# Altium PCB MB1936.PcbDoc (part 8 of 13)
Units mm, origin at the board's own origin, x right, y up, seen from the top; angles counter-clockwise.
Board outline 172 x 137 mm, 6 copper layers (Top Layer, Signal Layer 1, Signal Layer 2, Signal Layer 3, Signal Layer 4, Bottom Layer), stack 1.549 mm thick; 859 components, 672 nets, 3477 pads, 2222 vias.
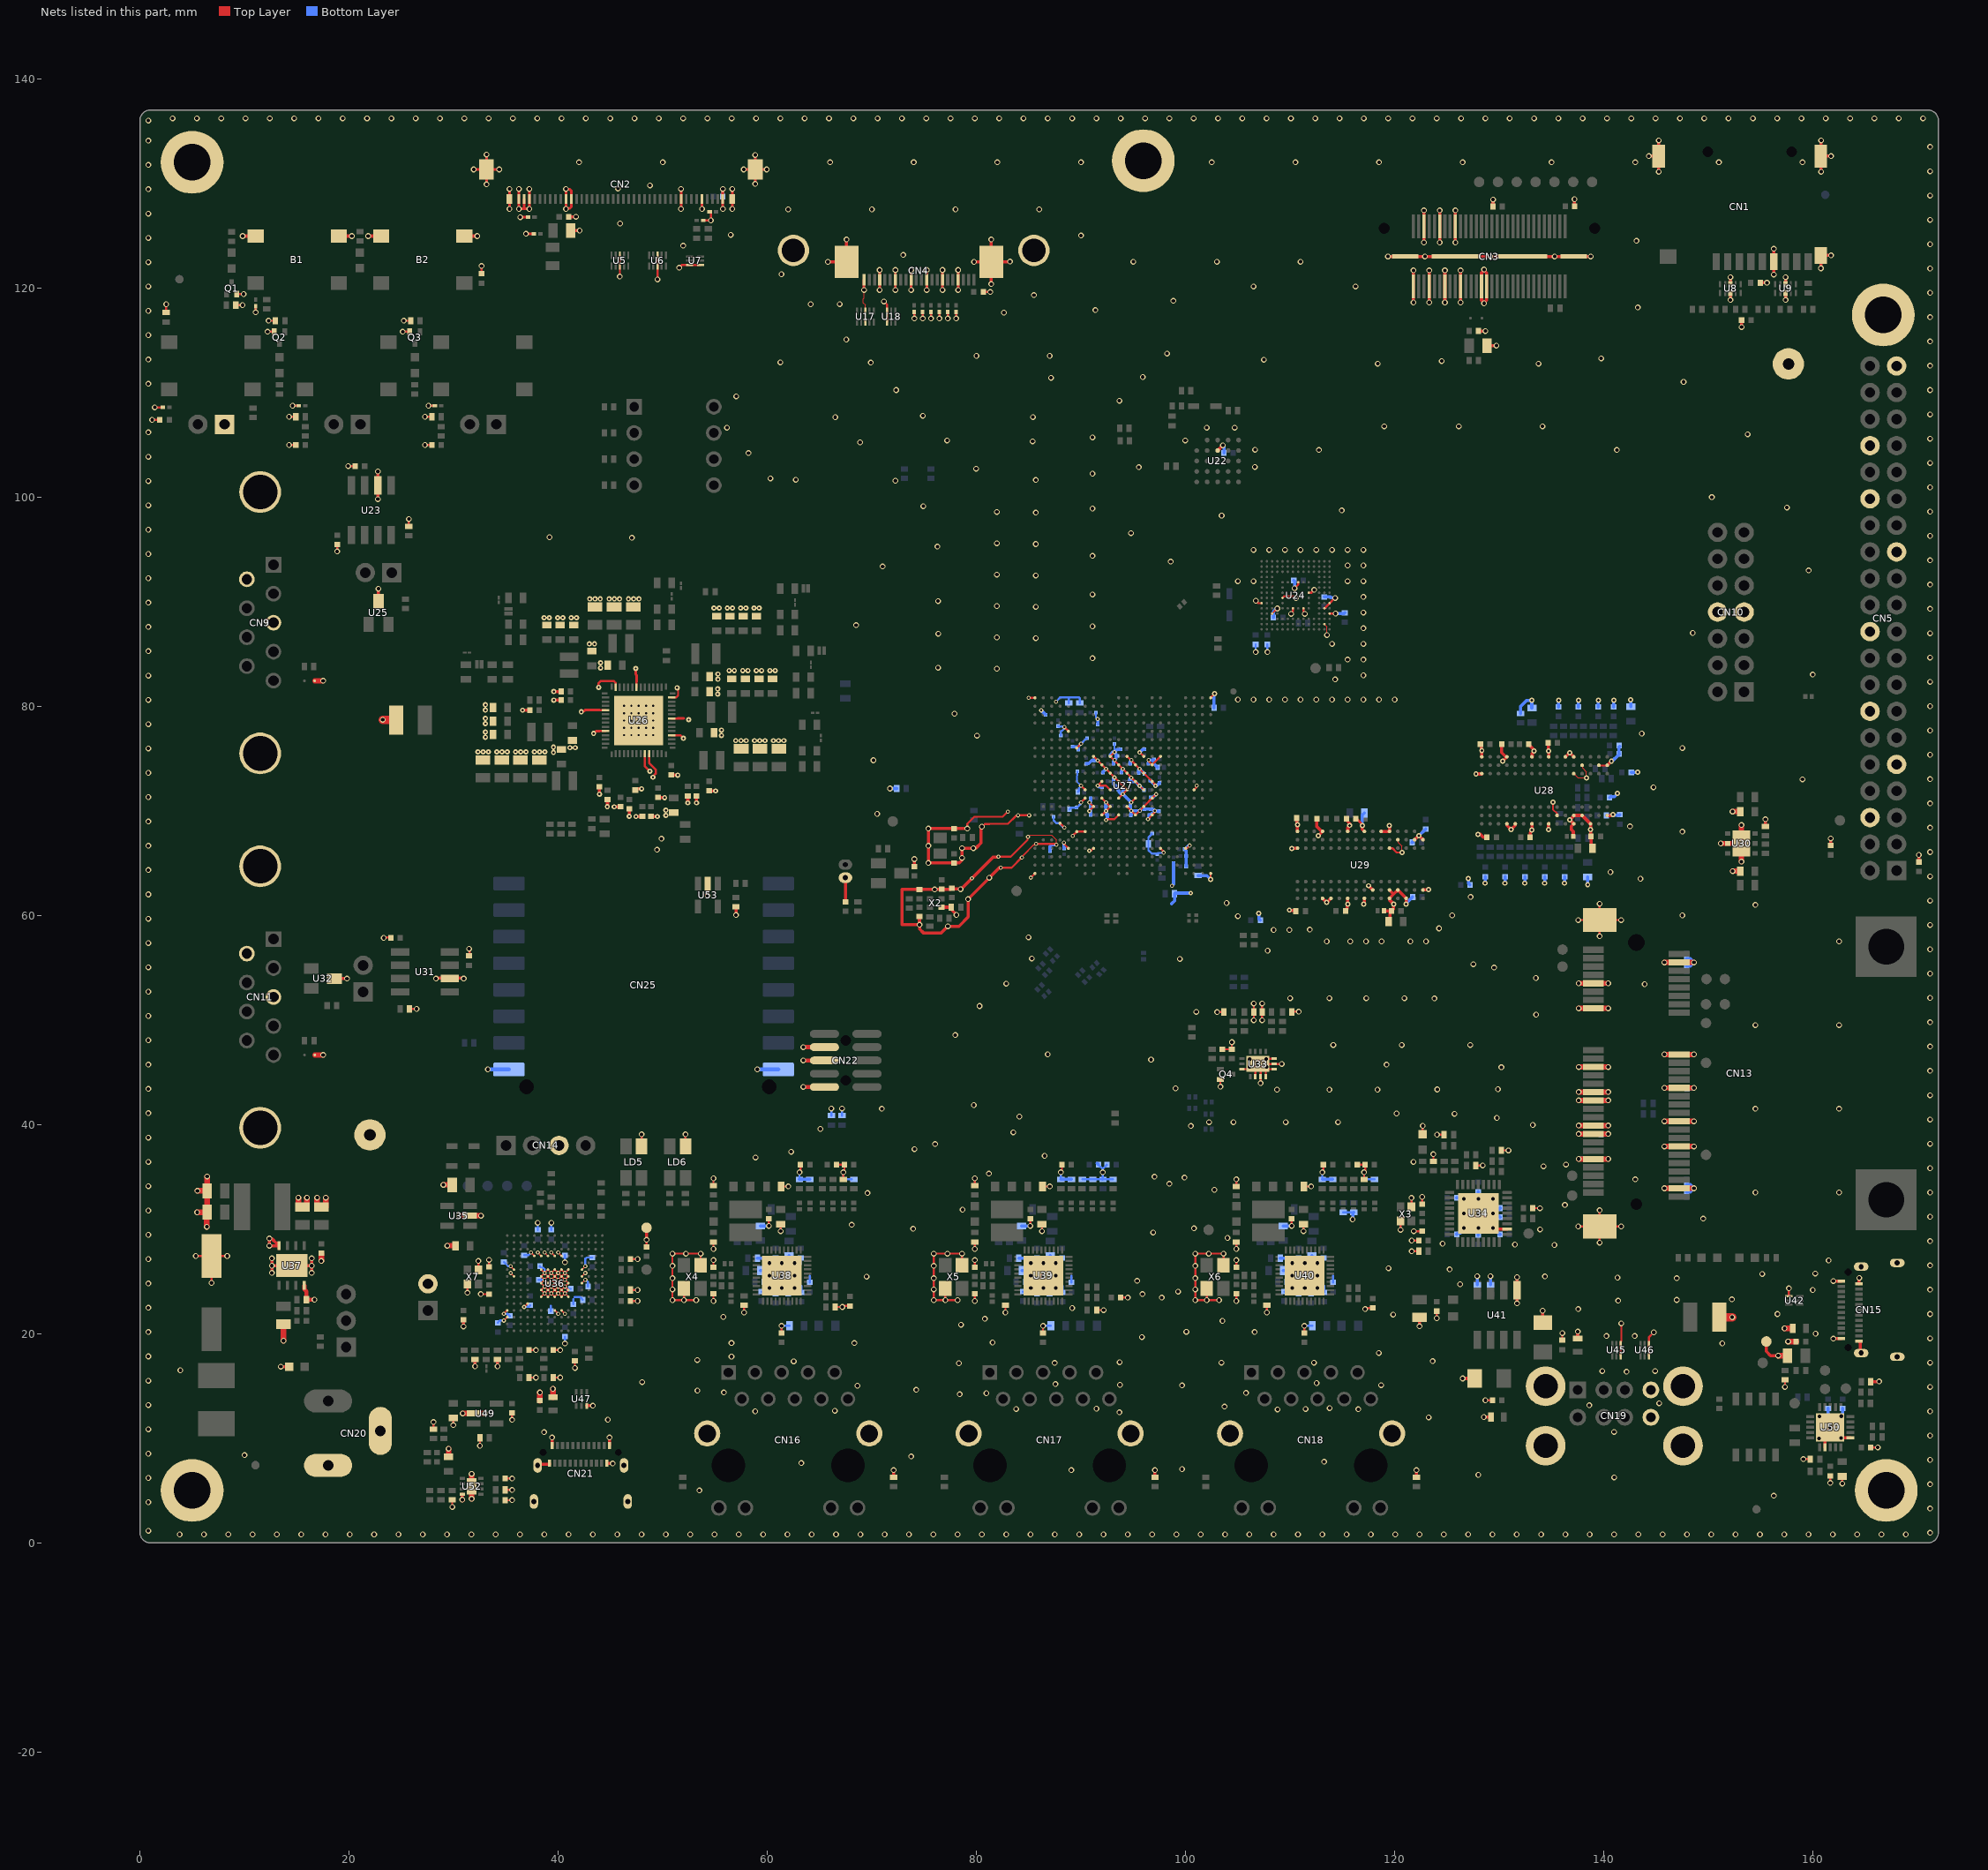
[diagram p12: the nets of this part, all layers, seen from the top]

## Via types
v1: diameter 0.55, hole 0.35, Top Layer to Bottom Layer, 1661 vias
v2: diameter 0.4, hole 0.2, Top Layer to Bottom Layer, tented both sides, 253 vias
v3: diameter 0.5, hole 0.2, Top Layer to Bottom Layer, 157 vias
v4: diameter 0.5, hole 0.25, Top Layer to Bottom Layer, 145 vias
v5: diameter 0.4, hole 0.2, Top Layer to Bottom Layer, 6 vias

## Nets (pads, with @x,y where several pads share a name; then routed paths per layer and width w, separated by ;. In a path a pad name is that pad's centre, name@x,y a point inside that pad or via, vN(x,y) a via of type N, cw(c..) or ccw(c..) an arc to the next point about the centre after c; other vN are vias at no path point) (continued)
GND: B1.3 B1.4 B2.1 B2.2 C1.1 C2.1 C3.1 C4.1 C5.1 C6.1 C7.1 C8.1 C9.1 C10.1 C11.1 C12.1 C13.1 C14.2 C15.1 C16.1 C17.1 C18.1 C21.1 C22.1 C23.1 C24.1 C26.1 C27.1 C28.1 C29.1 C30.1 C32.1 C34.1 C35.1 C36.1 C37.1 C38.1 C39.1 C40.1 C41.1 C42.2 C43.2 C44.1 C45.1 C46.1 C47.1 C48.1 C49.1 C50.1 C51.1 C52.1 C53.1 C54.1 C56.1 C57.1 C58.1 C59.1 C60.1 C61.1 C62.1 C63.2 C64.1 C65.2 C66.1 C67.1 C68.1 C69.2 C70.1 C71.1 C72.2 C73.2 C74.2 C75.2 C76.1 C77.1 C78.1 C79.1 C80.1 C81.2 C82.1 C83.1 C84.1 C85.1 C86.2 C87.1 C88.1 C89.1 C90.1 C91.1 C92.2 C93.1 C94.1 C95.1 C96.1 C99.1 C100.2 C101.1 C102.1 C103.1 C104.1 C105.1 C106.1 C107.1 C108.1 C109.1 C110.1 C111.1 C112.1 C113.2 C114.1 C115.1 C116.1 C117.1 C118.1 C119.1 C120.1 C121.1 C122.1 C123.1 C124.1 C125.1 C126.1 C127.2 C128.1 C129.1 C130.1 C131.1 C132.1 C133.2 C134.1 C135.1 C136.1 C137.1 C138.1 C139.1 C140.1 C141.1 C142.1 C143.1 C144.1 C145.1 C146.1 C147.2 C148.1 C149.1 C150.1 C152.1 C153.1 C154.1 C155.1 C156.1 C157.2 C158.2 C159.1 C160.1 C161.1 C163.1 C164.2 C165.1 C166.1 C168.1 C169.1 C170.1 C171.1 C172.1 C173.1 C174.1 C175.1 C177.1 C178.1 C179.1 C180.1 C181.1 C182.1 C183.1 C184.1 C185.1 C186.1 C187.1 C188.1 C189.1 C190.1 C191.1 C192.1 C193.1 C194.1 C195.1 C196.1 C197.1 C198.1 C199.1 C200.2 C201.1 C202.1 C203.1 C204.2 C205.1 C206.1 C207.1 C208.1 C209.1 C210.1 C211.1 C212.1 C213.1 C214.1 C215.2 C216.1 C217.1 C218.1 C219.2 C220.1 C221.1 C222.1 C223.1 C224.1 C225.1 C226.1 C227.1 C228.1 C229.2 C230.2 C231.1 C232.1 C233.2 C234.1 C235.1 C236.1 C237.1 C238.1 C239.1 C240.1 C241.2 C242.1 C243.1 C244.1 C245.1 C246.1 C247.1 C248.1 C249.1 C250.1 C251.1 C252.1 C253.1 C254.1 C255.1 C256.1 C257.1 C258.1 C259.1 C260.1 C261.1 C262.1 C264.1 C265.2 C266.2 C267.2 C268.2 C269.1 C270.1 C271.1 C272.2 C273.1 C274.2 C275.1 C276.1 C277.1 C278.1 C279.2 C280.2 C281.2 C282.2 C283.1 C284.1 C285.1 C286.1 C287.1 C288.1 C289.2 C290.2 C291.1 C292.1 C293.1 C294.1 C295.1 C296.1 C297.2 C298.2 C299.2 C300.1 C301.1 C302.1 C303.2 C304.1 C305.1 C306.1 C307.1 C308.1 C309.1 C310.2 C311.2 C312.1 C313.1 C314.1 C315.1 C316.1 C317.1 C318.1 C319.1 C320.1 C321.1 C322.1 C323.1 C324.2 C325.2 C326.2 C327.2 C328.2 C329.2 C330.1 C331.1 C332.1 C333.2 C334.2 C335.2 C336.1 CN1.6 CN1.10 CN1.11 CN1.12 CN2.1 CN2.5 CN2.9 CN2.30 CN2.31 CN2.38 CN2.39 CN2.40 CN2.41 CN2.42 CN2.43 CN2.44 CN3.1 CN3.6 CN3.7 CN3.12 CN3.13 CN3.18 CN3.19 CN3.27 CN3.29 CN3.61 CN3.62 CN3.63 CN3.64 CN4.1 CN4.4 CN4.7 CN4.10 CN4.13 CN4.16 CN4.19 CN4.S1 CN4.S2 CN5.6 CN5.9 CN5.14 CN5.20 CN5.25 CN5.30 CN5.34 CN5.39 CN6.1 CN9.3 CN9.6 CN9.MT1 CN9.MT2 CN10.7 CN10.8 CN11.3 CN11.6 CN11.MT1 CN11.MT2 CN12.2 CN13.4 CN13.9 CN13.15 CN13.18 CN13.21 CN13.26 CN13.27 CN13.29 CN13.34 CN13.35 CN13.37 CN13.40 CN13.43 CN13.50 CN13.53 CN13.54 CN14.3 CN15.A1 CN15.A12 CN15.B1 CN15.B12 CN15.SH1 CN15.SH2 CN15.SH3 CN15.SH4 CN16.15 CN16.16 CN17.15 CN17.16 CN18.15 CN18.16 CN19.B4 CN19.CH1 CN19.CH2 CN19.CH3 CN19.CH4 CN19.T4 CN20.2 CN20.3 CN21.A1 CN21.A12 CN21.B1 CN21.B12 CN21.SH1 CN21.SH2 CN21.SH3 CN21.SH4 CN22.3 CN22.5 CN22.9 CN25.8 CN25.9 JP3.2 LD5.3 LD6.3 LD11.2 LD12.2 pad.1 pad.5 pad.7 Q1.2 Q2.2 Q3.2 Q4.2 R8.1 R16.1 R17.1 R24.1 R25.1 R26.2 R34.2 R62.1 R63.1 R72.2 R73.1 R81.2 R82.2 R83.2 R84.1 R85.1 R95.1 R96.2 R98.1 R102.1 R105.1 R113.1 R123.1 R126.2 R127.2 R128.2 R158.1 R159.1 R160.1 R170.1 R194.2 R199.2 R200.2 R201.2 R204.1 R205.2 R206.2 R213.2 R215.2 R220.1 R221.2 R222.2 R226.2 R229.1 R231.2 R234.1 R236.1 R238.1 R239.1 R242.2 R244.1 R250.2 R251.2 R252.1 R262.1 R274.2 R285.1 R287.2 R292.1 R293.1 R294.1 R295.1 R296.1 R297.1 R298.1 R299.1 R300.1 R301.1 R302.1 R303.1 R304.1 R305.1 R306.1 R307.1 R320.1 R321.1 R322.1 R323.1 R324.1 R327.1 SB2.1 SB3.1 TP8.1 TP22.1 TP30.1 TP34.1 U1.2 U2.2 U3.2 U4.2 U5.3 U5.8 U6.3 U6.8 U7.3 U7.4 U8.3 U8.8 U9.3 U9.8 U10.2 U11.2 U12.2 U13.2 U14.2 U15.2 U16.2 U17.3 U17.8 U18.3 U18.4 U19.2 U20.2 U21.2 U22.B3 U23.2 U24.A6 U24.C4 U24.E7 U24.G5 U24.H10 U24.J5 U24.K8 U24.N2 U24.N5 U24.P4 U24.P6 U25.3 U26.9 U26.10 U26.18 U26.22 U26.27 U26.36 U26.41 U26.47 U26.52 U26.57 U27.A1 U27.A22 U27.AB1 U27.AB22 U27.E5 U27.G6 U27.H8 U27.H10 U27.H12 U27.H14 U27.H16 U27.J9 U27.J11 U27.J13 U27.J15 U27.K10 U27.K12 U27.K14 U27.L9 U27.L11 U27.L13 U27.L15 U27.M7 U27.M10 U27.M12 U27.M14 U27.M20 U27.N7 U27.N9 U27.N11 U27.N13 U27.N15 U27.P8 U27.P10 U27.P12 U27.P14 U27.R9 U27.R11 U27.R13 U27.R15 U27.T4 U27.U6 U27.U7 U27.W5 U27.W8 U27.W16 U27.W19 U28.A2 U28.A8 U28.B2 U28.C9 U28.D2 U28.D8 U28.E1 U28.E3 U28.E8 U28.E9 U28.F1 U28.G8 U28.H1 U28.H9 U28.K1 U28.K9 U28.M9 U28.N1 U28.N9 U28.T1 U28.T3 U29.A2 U29.A8 U29.B2 U29.C9 U29.D2 U29.D8 U29.E1 U29.E3 U29.E8 U29.E9 U29.F1 U29.G8 U29.H1 U29.H9 U29.K1 U29.K9 U29.M9 U29.N1 U29.N9 U29.T1 U29.T3 U30.2 U30.EP U31.2 U32.3 U33.2 U33.3 U33.4 U33.5 U33.6 U33.7 U33.14 U33.15 U34.11 U34.37 U35.2 U36.D5 U36.D6 U36.D7 U36.D8 U36.D9 U36.F2 U36.F6 U36.F7 U36.F8 U36.F9 U36.F10 U36.F12 U36.G2 U36.G6 U36.G7 U36.G8 U36.G9 U36.G10 U36.G12 U36.H6 U36.H7 U36.H8 U36.H9 U36.H10 U36.H12 U36.J6 U36.J7 U36.J8 U36.J9 U36.J10 U36.K6 U36.K7 U36.K8 U36.K9 U36.K10 U36.L4 U36.M1 U36.M8 U36.M9 U36.N1 U37.4 U37.8 U37.9 U38.41 U39.41 U40.41 U41.1 U42.4 U43.2 U44.2 U45.3 U45.4 U46.3 U46.4 U47.3 U48.2 U49.2 U50.12 U50.16 U50.21 U51.2 U52.8 U52.9 U53.2 X2.2 X3.2 X3.4 X4.2 X4.4 X5.2 X5.4 X6.2 X6.4 X7.2 X7.4 | length 825.9
  Top Layer w0.09: v2(84.925,67.5) 85.12,67.695 87.155,67.695 87.183,67.667 87.65,67.2 v2(87.65,66.75) ; U24.N2@113.275,87.85 113.525,87.6 v1(113.525,86.8) ; U29.A8@122.728,62.482 v4@123.061,62.482 ; U28.F1@136.307,75.146 U28.F1@136.326,75.127
  Top Layer w0.1: v1(69.25,119.8) 69.25,119.001 69.175,118.926 69.175,118.574 69.375,118.374 U17.3@69.375,117.775 ; v4@110.15,66.435 v4@110.155,66.43 ; v4@110.155,66.402 v4@110.155,66.43 ; v4@110.163,66.422 v4@110.155,66.43 ; U29.D2@120.3,67.225 120.343,67.183 120.343,66.972 120.7,66.615 v4(120.7,66.025) ; v4@127.782,73.538 v4@127.787,73.533 ; v4@127.787,73.505 v4@127.787,73.533 ; v4@127.795,73.525 v4@127.787,73.533 ; U28.E3@137.125,73.525 137.158,73.525 137.533,73.15 138.31,73.15 138.332,73.128 138.332,73.718 137.975,74.075 137.975,74.285 U28.D2@137.932,74.328
  Top Layer w0.15: v2(34.8,21.25) U36.N1@35.125,21.575 ; v2(34.8,21.9) U36.M1@35.125,22.225 ; v2(35.45,25.8) U36.G2@35.775,25.475 ; v2(35.45,26.45) U36.F2@35.775,26.125 ; v2(36.75,22.55) U36.L4@37.075,22.875 ; v2(37.4,27.75) U36.D5@37.725,27.425 ; v2(38.05,27.75) U36.D6@38.375,27.425 ; U36.K6@38.375,23.525 v2(38.7,23.85) ; U36.F6@38.375,26.125 v2(38.7,25.8) ; v2(38.7,27.75) U36.D7@39.025,27.425 ; v2(39.35,27.75) U36.D8@39.675,27.425 ; U36.M8@39.675,22.225 v2(40,21.9) ; v2(40,27.75) U36.D9@40.325,27.425 ; U36.M9@40.325,22.225 v2(40.65,21.9) ; U36.K10@40.975,23.525 v2(40.65,23.85) ; U36.F10@40.975,26.125 v2(40.65,25.8) ; U36.H12@42.275,24.825 v2(42.6,25.15) ; U36.G12@42.275,25.475 v2(42.6,25.8) ; U36.F12@42.275,26.125 v2(42.6,26.45) ; v2(84.345,65.531) 84.345,65.598 84.448,65.702 84.448,65.708 85.465,66.725 85.523,66.725 85.636,66.838 v2(85.703,66.838) ; v4(135.125,70.8) 135.125,70.125 135.525,69.725 U28.G8@135.525,69.55 ; U28.B2@139.525,74.35 139.566,74.31 140.285,74.31 U28.A2@140.325,74.35 ; v2(38.7,23.85) U36.K7@39.025,23.525 v2(39.35,23.85) ; v2(38.7,23.85) U36.J6@38.375,24.175 v2(38.7,24.5) ; v2(38.7,23.85) U36.J7@39.025,24.175 ; v2(38.7,24.5) U36.J7@39.025,24.175 ; v2(38.7,24.5) U36.H6@38.375,24.825 v2(38.7,25.15) ; v2(38.7,24.5) U36.H7@39.025,24.825 ; v2(38.7,25.15) U36.H7@39.025,24.825 ; v2(38.7,25.15) U36.G6@38.375,25.475 v2(38.7,25.8) ; v2(38.7,25.15) U36.G7@39.025,25.475 ; v2(38.7,25.8) U36.G7@39.025,25.475 ; v2(38.7,25.8) U36.F7@39.025,26.125 v2(39.35,25.8) ; U36.J7@39.025,24.175 v2(39.35,23.85) ; U36.J7@39.025,24.175 v2(39.35,24.5) ; U36.H7@39.025,24.825 v2(39.35,24.5) ; U36.H7@39.025,24.825 v2(39.35,25.15) ; U36.G7@39.025,25.475 v2(39.35,25.15) ; U36.G7@39.025,25.475 v2(39.35,25.8) ; v2(39.35,23.85) U36.K8@39.675,23.525 v2(40,23.85) ; v2(39.35,23.85) U36.J8@39.675,24.175 ; v2(39.35,24.5) U36.J8@39.675,24.175 ; v2(39.35,24.5) U36.H8@39.675,24.825 ; v2(39.35,25.15) U36.H8@39.675,24.825 ; v2(39.35,25.15) U36.G8@39.675,25.475 ; v2(39.35,25.8) U36.G8@39.675,25.475 ; v2(39.35,25.8) U36.F8@39.675,26.125 v2(40,25.8) ; U36.J8@39.675,24.175 v2(40,23.85) ; U36.J8@39.675,24.175 v2(40,24.5) ; U36.H8@39.675,24.825 v2(40,24.5) ; U36.H8@39.675,24.825 v2(40,25.15) ; U36.G8@39.675,25.475 v2(40,25.15) ; U36.G8@39.675,25.475 v2(40,25.8) ; v2(40,23.85) U36.K9@40.325,23.525 v2(40.65,23.85) ; v2(40,23.85) U36.J9@40.325,24.175 ; v2(40,24.5) U36.J9@40.325,24.175 ; v2(40,24.5) U36.H9@40.325,24.825 ; v2(40,25.15) U36.H9@40.325,24.825 ; v2(40,25.15) U36.G9@40.325,25.475 ; v2(40,25.8) U36.G9@40.325,25.475 ; v2(40,25.8) U36.F9@40.325,26.125 v2(40.65,25.8) ; U36.J9@40.325,24.175 v2(40.65,23.85) ; U36.J9@40.325,24.175 v2(40.65,24.5) ; U36.H9@40.325,24.825 v2(40.65,24.5) ; U36.H9@40.325,24.825 v2(40.65,25.15) ; U36.G9@40.325,25.475 v2(40.65,25.15) ; U36.G9@40.325,25.475 v2(40.65,25.8) ; v2(40.65,23.85) U36.J10@40.975,24.175 v2(40.65,24.5) ; v2(40.65,24.5) U36.H10@40.975,24.825 v2(40.65,25.15) ; v2(40.65,25.15) U36.G10@40.975,25.475 v2(40.65,25.8)
  Top Layer w0.2: v1(1.425,108.575) 1.438,108.563 U21.2@2.188,108.563 ; R26.2@2.5,117.637 2.5,118.4 v1(2.525,118.425) ; v1(5.35,27.425) C127.2@6.85,27.425 ; v1(6.85,24.85) C127.2@6.85,27.425 ; v1(8.35,27.425) C127.2@6.85,27.425 ; R8.1@9.173,118.35 v1(9.823,118.35) ; Q1.2@9.273,119.4 v1(9.923,119.4) ; v1(11.073,117.663) U10.2@11.073,118.25 U10.2@11.073,118.263 ; v1(12.213,115.8) Q2.2@12.863,115.8 ; v1(12.313,116.85) R16.1@12.963,116.85 ; v1(14.263,104.975) C11.1@14.913,104.975 ; v1(14.263,107.675) R24.1@14.913,107.675 ; v1(14.6,108.725) U19.2@15.2,108.725 ; v1(18.869,94.796) C15.1@18.869,95.461 C15.1@18.869,95.471 ; v1(19.919,102.956) C14.2@20.594,102.956 ; v1@23.37,57.9 C96.1@24.045,57.9 ; v1(25.137,115.8) Q3.2@25.787,115.8 ; v1(25.238,116.85) R17.1@25.888,116.85 ; R34.2@25.721,97.216 v1(25.721,97.891) ; R81.2@25.79,51.048 v1(26.465,51.048) ; v1(27.263,104.975) C12.1@27.913,104.975 ; v1(27.263,107.675) R25.1@27.913,107.675 ; v1(27.6,108.725) U20.2@28.2,108.725 ; R226.2@28.07,10.875 v1(28.07,11.55) ; v1(29.87,3.425) R242.2@29.87,4.1 ; v1(29.975,11.25) C165.1@29.975,11.925 ; v1(31.325,23.905) X7.2@31.325,24.75 ; C100.2@31.53,56.175 v1@31.53,56.85 ; v1(32.37,26.95) 32.37,26.105 X7.4@32.375,26.1 ; v1(32.525,9.275) R229.1@32.525,10.05 ; v1(32.6,23.775) C140.1@33.395,23.775 ; C133.2@33.395,26.375 v1(33.395,27.05) ; C173.1@34.925,4.075 v1(35.6,4.075) ; R239.1@34.925,5.05 v1(35.6,5.05) ; C172.1@34.925,6.15 v1(35.6,6.15) ; v1(35.6,11.75) C166.1@35.6,12.425 ; R221.2@37.205,15.8 v1(37.88,15.8) ; C157.2@37.205,18.425 v1(37.88,18.425) ; R222.2@39.525,15.8 v1(40.2,15.8) ; C158.2@39.525,18.425 v1(40.2,18.425) ; v1(41.6,16.725) C160.1@41.6,17.4 ; v1(45.9,121.075) U5.8@45.9,122.075 U5.3@45.9,123.125 ; C145.1@46.925,23.125 v1(47.6,23.125) ; R194.2@46.925,24.175 v1(47.6,24.175) ; C132.1@46.925,27.125 v1(47.6,27.125) ; LD5.3@47.975,37.9 v1(47.975,39.05) ; C131.1@48.45,28.3 v1(48.45,28.975) ; v1(49.5,120.8) U6.8@49.5,122.075 U6.3@49.5,123.125 ; U26.27@50.87,80.827 51.279,80.827 51.47,81.018 51.47,81.737 v3@51.516,81.783 ; v3(51.37,81.757) v3@51.427,81.7 ; v1(51.575,121.925) 51.85,122.2 U7.3@52.575,122.2 U7.4@53.625,122.2 ; X4.2@52.025,24.325 v1(52.025,23.2) ; LD6.3@52.175,37.9 v1(52.175,39.05) ; v1(53.2,23.2) v1(52.025,23.2) ; X4.4@53.625,26.525 v1(53.625,27.65) v1(52.225,27.65) v1(50.925,27.65) v1(50.925,26.475) v1(50.925,25.3) v1(50.925,24.225) v1(50.925,23.2) v1(52.025,23.2) ; U3.2@53.875,126.45 53.878,126.453 54.478,126.453 v1@54.488,126.463 ; U1.2@54.488,127.275 54.6,127.163 v1(54.6,126.45) ; v1(54.85,23.125) C137.1@54.85,23.8 ; C134.1@54.85,26.35 v1(54.85,27.025) ; v1(54.85,28.095) R158.1@54.85,28.77 ; R126.2@54.85,34.17 v1(54.85,34.845) ; v1(57.775,22.025) R199.2@57.775,22.7 ; v1(60.15,30.3) C123.1@60.15,30.975 ; v1(61.275,29.8) C120.1@61.275,30.475 ; C111.1@61.32,34.07 v1(62.015,34.07) ; C152.1@61.365,20.075 v1(61.365,20.75) ; v1(63.075,35.425) 63.175,35.525 C103.1@63.175,36.17 ; R205.2@66.495,22.55 v1(67.17,22.55) 67.27,22.65 C141.1@67.9,22.65 ; C104.1@66.625,36.17 67.355,36.17 C109.1@67.375,36.15 67.375,35.525 v1(67.275,35.425) R113.1@67.275,34.75 ; U17.8@69.375,116.725 U17.3@69.375,117.775 ; v1(71.15,118.7) 71.45,118.4 U18.3@71.45,117.775 U18.4@71.45,116.725 ; v1(74.06,117.062) U11.2@74.06,117.687 ; v1(74.86,117.062) U12.2@74.86,117.687 ; v1(75.66,117.062) U13.2@75.66,117.687 ; v1(76.46,117.062) U14.2@76.46,117.687 ; X5.2@77.025,24.325 v1(77.025,23.2) ; v1(77.26,117.062) U15.2@77.26,117.687 ; v1(78.06,117.062) U16.2@78.06,117.687 ; v1(78.2,23.2) v1(77.025,23.2) ; X5.4@78.625,26.525 v1(78.625,27.65) v1(77.225,27.65) v1(75.925,27.65) v1(75.925,26.475) v1(75.925,25.3) v1(75.925,24.225) v1(75.925,23.2) v1(77.025,23.2) ; v1(79.125,68.3) 79.125,68.75 79.8,69.425 82.507,69.425 v2(83.002,69.92) ; v1(79.85,23.125) C138.1@79.85,23.8 ; C135.1@79.85,26.35 v1(79.85,27.025) ; v1(79.85,28.095) R159.1@79.85,28.77 ; R127.2@79.85,34.17 v1(79.85,34.845) ; v1(80.525,68.475) 80.568,68.475 80.818,68.725 81.262,68.725 81.287,68.75 83.012,68.75 83.784,69.522 83.94,69.522 v2(83.978,69.56) v2(85.046,69.56) ; C7.1@80.65,119.6 v1(81.325,119.6) ; v2(82.1,65.6) 83.28,65.6 83.703,66.023 84.887,67.207 84.887,67.462 v2(84.925,67.5) ; v2(82.325,64.55) 83.364,64.55 v2(84.345,65.531) ; v1(82.775,22.025) R200.2@82.775,22.7 ; v2(85,80.805) 85.005,80.8 U27.A1@85.6,80.8 ; v1(85.15,30.3) C124.1@85.15,30.975 ; v2(85.2,63.6) U27.AB1@85.6,64 ; v2(85.703,66.838) 87.508,66.838 87.596,66.75 v2(87.65,66.75) ; v1(86.275,29.8) C121.1@86.275,30.475 ; C112.1@86.32,34.07 v1(87.015,34.07) ; C153.1@86.365,20.075 v1(86.365,20.75) ; U27.T4@88,68.8 v2(88.4,68.4) ; v1(88.075,35.425) 88.175,35.525 C105.1@88.175,36.17 ; v2(88.37,66.944) 88.408,66.905 88.408,66.792 U27.W5@88.8,66.4 ; v2(88.4,78) U27.E5@88.8,77.6 ; v2(89.2,67.6) U27.U6@89.6,68 U27.U7@90.4,68 ; U27.G6@89.6,76 v2(90,76.4) ; v2(90,70.8) U27.N7@90.4,71.2 ; v2(90,72.4) U27.M7@90.4,72 ; v2(90.788,66.173) 90.827,66.211 90.984,66.211 91.173,66.4 U27.W8@91.2,66.4 ; v2@90.8,70 U27.P8@91.2,70.4 v2(90.8,70.8) ; U27.H8@91.2,75.2 v2(91.6,74.8) U27.J9@92,74.4 v2(92.4,74) v2@93.225,73.175 ; R206.2@91.495,22.25 v1(92.17,22.25) ; U27.R9@92,69.6 92.025,69.6 v2(92.4,69.975) 92.8,70.375 U27.P10@92.8,70.4 v2(92.4,70.8) U27.N9@92,71.2 ; U27.L9@92,72.8 v2(91.6,72.4) 92.4,72.4 U27.M10@92.8,72 ; v2@92.454,69.1 v2(92.4,69.1) 92.5,69.2 93.2,69.2 U27.R11@93.6,69.6 ; v2(93.2,73.175) v2@93.225,73.175 ; v2(93.201,75.6) 92.801,75.2 v2@93.226,74.775 ; v2(93.226,74.85) v2@93.226,74.775 ; U27.N11@93.6,71.2 v2(94,71.6) U27.M12@94.4,72 v2@93.225,73.175 ; C142.1@93.8,23.45 v1(94.475,23.45) ; U27.P12@94.4,70.4 v2(94.8,70) U27.R13@95.2,69.6 95.787,70.188 ; U27.H12@94.407,75.2 94.757,74.85 v2(94.832,74.85) 94.832,74.775 v2(95.607,74) U27.L15@96.807,72.8 ; v2(94.8,70.8) U27.N13@95.2,71.2 ; v2@95.625,75.575 U27.H14@96,75.2 ; U27.P14@96,70.4 95.787,70.188 ; U27.M14@96,72 95.626,72.375 94.851,73.15 v2(94.801,73.15) 94.801,73.2 v2(94.001,74) v2@93.226,74.775 ; v2(96.4,69.2) v2@97.05,69.85 ; v2(96.475,74.85) 96.514,74.812 96.514,74.686 U27.J15@96.8,74.4 U27.H16@97.6,75.2 ; U27.L15@96.8,72.8 97.087,72.513 97.087,72.413 v2(97.125,72.375) ; v2(97.175,71.575) 95.787,70.188 ; U27.W16@97.6,66.4 97.862,66.138 97.862,66.038 v2(97.9,66) ; U27.W19@100,66.4 100.019,66.419 100.144,66.419 v2(100.4,66.675) ; U27.M20@100.825,72 U27.M20@100.8,72 101.018,72.218 101.018,72.343 v2(101.075,72.4) v2@101.075,72.329 ; X6.2@102.025,24.325 v1(102.025,23.2) ; v4(102.4,63.45) U27.AB22@102.4,64 ; U27.A22@102.4,80.8 102.4,80.811 102.75,81.161 v4@102.75,81.175 ; v1(103.025,50.74) 103.65,50.74 R82.2@103.675,50.765 ; v1(103.2,23.2) v1(102.025,23.2) ; v1(103.325,43.615) Q4.2@103.325,44.29 ; C101.1@103.525,47.19 C102.1@104.425,47.19 v1(104.425,47.865) ; X6.4@103.625,26.525 v1(103.625,27.65) v1(102.225,27.65) v1(100.925,27.65) v1(100.925,26.475) v1(100.925,25.3) v1(100.925,24.225) v1(100.925,23.2) v1(102.025,23.2) ; v1(104.85,23.125) C139.1@104.85,23.8 ; C136.1@104.85,26.35 v1(104.85,27.025) ; v1(104.85,28.095) R160.1@104.85,28.77 ; R128.2@104.85,34.07 v1(104.85,34.745) ; U33.14@105.375,45.29 106.425,45.29 U33.15@106.675,45.54 ; v1(106.525,49.965) 106.525,50.015 R83.2@106.525,50.765 106.525,51.515 v1(106.525,51.565) ; U33.2@106.675,44.59 U33.15@106.675,45.54 ; v1(106.725,90.075) 106.95,89.85 U24.A6@107.275,89.85 ; v1(107.175,43.945) U33.3@107.175,44.59 107.175,45.54 U33.15@106.925,45.79 ; v1(107.325,49.965) 107.325,50.015 R84.1@107.325,50.765 107.325,51.515 v1(107.325,51.565) ; U33.4@107.675,44.59 107.675,45.14 U33.15@107.55,45.265 ; v1(107.775,22.025) R201.2@107.775,22.7 ; U24.C4@108.275,88.85 108.725,89.3 108.735,89.3 v1(108.775,89.34) ; U33.5@108.475,45.29 107.575,45.29 U33.15@107.55,45.265 ; U33.7@108.475,46.29 107.425,46.29 U33.15@106.925,45.79 ; v1(109.2,45.79) U33.6@108.475,45.79 U33.15@107.025,45.79 ; U24.E7@109.275,90.35 109.425,90.5 110.312,90.5 110.487,90.325 v1(110.575,90.325) ; v1(110.1,88.825) 110.1,88.913 110.275,89.088 U24.G5@110.275,89.35 ; v1(110.15,30.3) C125.1@110.15,30.975 ; R85.1@110.175,50.765 110.2,50.79 v1(110.825,50.79) ; v1(110.425,91.275) 110.775,91.625 U24.H10@110.775,91.85 ; v1(111.275,29.8) C122.1@111.275,30.475 ; U24.J5@111.275,89.35 111.275,89.045 111.4,88.92 v1(111.4,88.825) ; C113.2@111.32,34.07 v1(112.015,34.07) ; C154.1@111.365,20.075 v1(111.365,20.75) ; U24.K8@111.775,90.85 112.025,90.85 v1(112.3,91.125) ; v1(113.075,35.425) 113.175,35.525 C106.1@113.175,36.17 ; U24.N5@113.275,89.35 U24.P6@113.775,89.85 114.275,90.35 v1(114.3,90.35) ; U24.P4@113.775,88.85 v1(114.35,88.85) ; C107.1@116.425,36.17 C108.1@117.155,36.17 117.175,36.15 117.175,35.525 v1(117.075,35.425) R123.1@117.075,34.75 ; v1(117.17,22.35) 117.27,22.45 C144.1@117.9,22.45 ; U29.E3@119.5,66.425 119.503,66.422 119.769,66.422 120.18,66.012 120.687,66.012 v4(120.7,66.025) ; v1(120.555,29.93) X3.4@120.555,30.775 ; v1(121.6,32.975) 121.6,32.13 X3.2@121.605,32.125 ; v1(121.625,27.875) R170.1@122.3,27.875 ; v1(121.625,28.9) C128.1@122.3,28.9 ; v1(121.83,29.8) C126.1@122.625,29.8 ; C115.1@122.625,32.4 v1(122.625,33.075) ; LD12.2@122.675,39.075 v1(122.675,39.875) ; R102.1@123.7,36.475 v1(123.7,37.15) ; v1(124.025,21.475) C146.1@124.025,22.15 ; v1(124.05,39.025) R95.1@124.725,39.025 ; R105.1@127.75,36.08 v1(128.425,36.08) ; v1(128.67,13.626) C163.1@129.345,13.626 ; R98.1@130.2,37.525 v1(130.875,37.525) ; C119.1@133.211,32 v1(133.886,32) ; C155.1@136.025,19.375 v1(136.025,20.05) ; v1(137.55,30.25) CN13.54@139.6,30.25 ; v1(137.55,59.55) CN13.53@139.6,59.55 ; v1(139.6,28.7) CN13.54@139.6,30.25 ; v1(139.6,31.8) CN13.54@139.6,30.25 ; v1(139.6,58) CN13.53@139.6,59.55 ; v1(139.6,61.1) CN13.53@139.6,59.55 ; U45.3@141.6,17.9 U45.4@141.6,18.95 141.6,19.2 141.675,19.275 v1(141.675,20.975) ; v1(141.65,30.25) CN13.54@139.6,30.25 ; v1(141.65,59.55) CN13.53@139.6,59.55 ; U46.3@144.3,17.9 U46.4@144.3,18.95 144.3,19.65 v1(144.775,20.125) ; v1(157.325,14.9) R220.1@157.325,15.575 ; U42.4@157.7,23.575 v1(157.7,24.325) ; v1(159.075,8) R231.2@159.75,8 ; v1(161.65,5.725) C171.1@161.65,6.4 ; U50.21@161.65,11.05 U50.21@162.65,10.05 ; v1(162.8,5.67) C170.1@162.8,6.345 ; C168.1@165.525,9.125 v1(166.2,9.125) ; U33.15@106.675,45.54 U33.15@106.925,45.79 ; U33.15@106.925,45.79 U33.15@107.025,45.79 ; U33.15@107.025,45.79 U33.15@107.55,45.265
  Top Layer w0.21: v3(43.875,81.802) 43.875,82.202 44.08,82.407 45.309,82.407 45.5,82.216 U26.41@45.5,81.797 ; 43.975,77.627 U26.52@44.53,77.627 ; 43.975,79.627 U26.47@44.53,79.627 ; U26.36@47.5,81.797 47.5,82.352 ; U26.9@48.3,75.457 48.3,74.247 v3(48.768,73.779) ; U26.10@48.7,75.457 48.7,74.561 49.335,73.926 49.335,73.547 49.07,73.283 v3(49.07,73.204) ; U26.18@50.87,77.227 51.672,77.227 v3(51.972,76.927) ; U26.22@50.87,78.827 51.425,78.827
  Top Layer w0.25: v1(1.175,107.375) C13.1@1.913,107.375 ; v1(31.925,131.32) CN2.44@33.145,131.32 ; C5.1@32.675,121.35 v1(32.675,122.088) ; v1(33.15,129.895) CN2.44@33.15,131.315 ; v1(33.15,132.745) CN2.44@33.15,131.32 ; v1(34.365,131.32) CN2.44@33.15,131.32 ; v1(35.35,127.55) CN2.43@35.35,128.5 v1(35.35,129.45) ; v1(36.25,129.45) CN2.40@36.25,128.5 v1(36.25,127.55) 36.75,127.55 ; v1(36.375,126.75) U2.2@37.113,126.75 ; CN2.39@36.75,128.5 36.75,127.55 ; v1(36.925,125.175) U4.2@37.663,125.175 ; v1(37.25,129.45) CN2.38@37.25,128.5 v1(37.25,127.55) 36.75,127.55 ; v3(42.208,79.452) 42.256,79.5 42.457,79.5 42.584,79.627 43.975,79.627 ; v3(43.388,77.39) 43.421,77.39 43.659,77.627 43.975,77.627 ; v3(47.425,83.602) 47.425,83.041 47.5,82.966 47.5,82.352 ; 51.425,78.827 52.03,78.827 ; v1(51.75,127.55) CN2.9@51.75,128.5 v1(51.75,129.45) ; v3@51.957,76.927 v3(51.972,76.927) ; v1(53.75,127.55) CN2.5@53.75,128.5 ; v1(55.75,127.55) CN2.1@55.75,128.5 v1(55.75,129.45) ; v1(56.65,127.55) CN2.42@56.65,128.5 v1(56.65,129.45) ; v1(57.75,131.32) CN2.41@58.85,131.32 ; v1(58.85,129.94) CN2.41@58.85,131.32 ; v1(58.85,132.7) CN2.41@58.85,131.32 ; v1(59.95,131.32) CN2.41@58.85,131.32 ; v1(69.25,119.8) CN4.1@69.25,120.75 ; v1(70.75,119.8) CN4.4@70.75,120.79 v1(70.75,121.7) ; v1(72.25,119.8) CN4.7@72.25,120.79 v1(72.25,121.7) ; v1(73.75,119.8) v1(73.75,121.7) ; v1(75.25,119.8) CN4.13@75.25,120.79 v1(75.25,121.7) ; v1(76.75,119.8) CN4.16@76.75,120.79 v1(76.75,121.7) ; v1(78.25,119.8) CN4.19@78.25,120.79 v1(78.25,121.7) ; C80.1@116.275,69.25 116.35,69.25 116.695,68.905 116.695,68.877 116.827,68.745 116.855,68.745 116.862,68.738 v4@116.862,68.613 ; CN2.44@33.145,131.32 CN2.44@33.15,131.315 ; CN2.44@33.145,131.32 CN2.44@33.15,131.32 ; CN2.44@33.15,131.315 CN2.44@33.15,131.32 ; v1(40.75,127.55) 40.797,127.597 41.122,127.597 41.25,127.725 CN2.30@41.25,128.5 41.25,129.275 41.122,129.403 40.797,129.403 v1(40.75,129.45) CN2.31@40.75,128.5 v1(40.75,127.55)
  Top Layer w0.3: v1(9.828,124.95) B1.4@11.073,124.95 ; v1(12.625,25.8) v1(12.625,26.5) ; v1(12.625,27.2) v1(12.625,26.5) ; U37.8@13.325,28.136 U37.8@13.325,28.4 ; v1(13.475,16.85) LD11.2@14.15,16.85 ; v1(16.425,25.8) v1(16.425,26.5) ; v1(16.425,27.2) v1(16.425,26.5) ; U32.3@18.605,53.95 v1(19.805,53.95) ; B1.3@19.023,124.95 v1(20.268,124.95) ; v1(21.828,124.95) B2.1@23.073,124.95 ; v1(22.764,99.796) U23.2@22.764,101.111 v1(22.764,102.446) ; U25.3@22.819,90.031 v1(22.819,91.231) ; v1@28.37,54.005 v1@31.02,54.005 ; v1(30.825,4.125) U52.8@30.825,4.65 ; v1(30.95,20.68) C149.1@30.95,21.325 ; B2.2@31.023,124.95 v1(32.268,124.95) ; v1(32.05,16.88) R213.2@32.05,17.525 ; v1(34.2,16.88) R215.2@34.2,17.525 ; v3(36.595,79.617) C43.2@37.255,79.617 ; CN21.SH1@38.035,7.4 38.14,7.505 39.165,7.505 CN21.B12@39.165,7.61 ; CN21.A1@39.415,9.31 v1(39.415,10.063) ; v3(39.585,80.577) C40.1@40.195,80.577 ; v3(39.585,81.402) C39.1@40.195,81.402 ; C3.1@41,126.8 v1(41.7,126.8) ; C4.1@41.2,125.475 v1(42.05,125.475) ; U47.3@42.725,13.114 v1(43.325,13.114) ; v3@43.95,71.637 C63.2@43.95,72.247 ; CN21.B1@44.665,7.61 44.665,7.598 45.202,7.598 v1(45.215,7.585) ; v3@44.7,70.432 C70.1@44.7,71.042 ; v3@44.725,70.462 C70.1@44.725,71.072 ; CN21.A12@44.915,9.31 v1(44.915,10.063) ; v3(45.365,70.377) C72.2@45.975,70.377 ; v3@46.8,69.517 C73.2@46.8,70.127 ; C64.1@47.375,72.097 v3(47.985,72.097) ; v3(47.44,69.447) C74.2@48.05,69.447 ; v1(48.45,28.975) TP30.1@48.45,30.125 ; C75.2@48.875,69.447 v3(49.485,69.447) ; C68.1@49.55,71.247 v3(50.185,71.247) ; C61.1@50.825,73.397 v3(51.435,73.397) ; v3(52.4,70.755) C66.1@52.4,71.415 ; v3(53.225,70.757) C67.1@53.225,71.417 ; v1(54.3,61.875) 54.312,61.887 U53.2@54.312,63.038 ; C65.2@54.45,71.892 v3(55.06,71.892) ; v1(57,60.025) R244.1@57,60.8 ; v1(65.8,122.475) 65.815,122.49 CN4.S1@67.58,122.49 67.58,124.62 v1(67.575,124.625) ; C88.1@67.475,61.3 CN12.2@67.475,63.6 ; R234.1@72.075,6.275 v1(72.075,6.95) ; C87.1@74.062,64.675 v1(74.062,65.375) ; C92.2@74.55,59.875 v1(74.55,59.1) ; v1(75.4,65) C86.2@77.85,65 ; 75.4,65.275 v1(75.4,66.65) v1(75.4,68.3) C81.2@77.85,68.3 v1(79.125,68.3) ; X2.2@76.648,60.776 R72.2@77.6,60.775 R72.2@77.6,60.775 77.705,60.67 77.705,60.47 78.083,60.093 v1(78.083,60.032) ; C86.2@77.955,65.105 C86.2@77.85,65 ; v1(78.475,62.5) 78.525,62.5 v2(79.575,63.55) 81.606,65.581 v2@82.081,65.581 ; v1@78.475,62.514 77.736,62.514 C90.1@77.65,62.6 77.625,62.6 77.5,62.475 76.675,62.475 76.663,62.488 76.013,62.488 v1(76,62.475) C91.1@74.55,62.475 72.875,62.475 72.875,59.1 v1(74.55,59.1) ; v1(79.775,122.475) 81.405,122.475 CN4.S2@81.42,122.49 ; v1(80.525,68.475) 80.43,68.38 80.43,66.905 79.993,66.468 79.748,66.468 v1(79.7,66.42) 79.695,66.425 v1(78.625,66.425) v1(78.625,65.5) 78.578,65.452 78.578,65.239 78.339,65 C86.2@77.85,65 ; v1@81.42,120.36 CN4.S2@81.42,122.49 ; v1@81.42,124.62 CN4.S2@81.42,122.49 ; v2(82.325,64.55) 82.306,64.531 82.156,64.531 v1(81.225,63.6) 81.225,63.575 v1(79.2,61.55) 79.225,61.525 79.225,59.85 78.325,58.95 v1(77.275,58.95) 77.25,58.95 76.625,58.325 74.925,58.325 74.563,58.687 74.563,59.087 v1(74.55,59.1) ; v1@83.185,122.49 CN4.S2@81.42,122.49 ; R236.1@97.075,6.275 v1(97.075,6.95) ; U22.B3@103.066,104.441 v1(103.566,104.941) ; v4@109.911,60.486 v4(109.925,60.5) 109.964,60.462 110.489,60.462 C95.1@110.55,60.4 ; v4@110.155,66.402 110.166,66.413 110.688,66.413 U29.T3@110.7,66.425 ; C77.1@110.625,69.3 110.663,69.263 110.663,68.688 v4(110.7,68.65) U29.T1@110.7,68.025 ; C78.1@112.55,69.25 112.55,68.498 113.023,68.025 U29.N1@113.1,68.025 v4(112.7,67.625) ; U29.N9@113.1,61.625 v4(113.5,61.225) U29.M9@113.9,61.625 ; C94.1@115.294,60.422 115.294,60.447 115.462,60.615 115.462,61.037 v4(115.5,61.075) U29.K9@115.5,61.625 ; C79.1@115.375,69.25 115.375,69.1 115.7,68.775 v4(115.7,68.6) 115.7,68.546 115.52,68.365 U29.K1@115.52,68.05 ; v4@116.862,68.613 v4(116.9,68.575) 116.9,68.225 U29.H1@117.1,68.025 ; v4(117.05,61.075) 117.1,61.125 U29.H9@117.1,61.625 ; v4(117.5,62.825) U29.G8@117.9,62.425 ; U29.F1@118.7,68.025 U29.E1@119.5,68.025 v4(119.5,68.575) ; R73.1@118.975,60.422 C93.1@119.569,60.422 ; v1(119.356,123) CN3.61@120.987,123 v1(122.9,123) CN3.62@125.875,123 v1(129.15,123) CN3.63@132.225,123 v1(135.3,123) CN3.64@137.113,123 v1(138.744,123) ; C99.1@119.425,59.4 119.55,59.525 119.55,60.3 119.9,60.65 v4(119.9,61.075) 119.52,61.456 U29.E9@119.52,61.606 ; U29.E8@119.5,62.409 119.894,62.015 119.894,62.009 ; U29.E9@119.51,61.625 119.894,62.009 ; U29.D8@120.3,62.415 119.894,62.009 ; U29.D8@120.3,62.425 U29.C9@121.1,61.625 v4(121.1,61.075) ; v1(121.8,118.6) CN3.1@121.8,120.13 v1(121.8,121.66) ; U29.B2@121.9,67.225 v4(122.3,67.625) U29.A2@122.7,67.225 ; R238.1@122.075,6.275 v1(122.075,6.95) ; v1(122.375,20.7) C143.1@122.375,21.55 ; U29.A8@122.7,62.425 v4@123.2,62.425 ; v1(122.8,124.34) CN3.6@122.8,125.87 v1(122.8,127.4) ; v1(123.3,118.6) CN3.7@123.3,120.13 v1(123.3,121.66) ; v1(124.3,124.34) CN3.12@124.3,125.87 v1(124.3,127.4) ; v1(124.8,118.6) CN3.13@124.8,120.13 v1(124.8,121.66) ; v1(125.8,124.34) CN3.18@125.8,125.87 v1(125.8,127.4) ; v1(126.3,118.6) CN3.19@126.3,120.13 v1(126.3,121.66) ; v1(126.5,15.715) C161.1@127.645,15.715 ; v4@127.787,73.505 127.797,73.515 128.32,73.515 U28.T3@128.332,73.528 ; v4(127.95,67.75) 128.175,67.75 128.475,67.45 C83.1@128.825,67.45 C83.1@128.85,67.45 ; C9.1@128.023,115.875 v1(128.673,115.875) ; C51.1@128.195,76.365 128.159,76.401 C51.1@128.295,76.401 ; C51.1@128.295,76.365 128.295,75.79 128.332,75.753 U28.T1@128.332,75.128 ; v1(128.525,12.025) U51.2@129.195,12.025 ; v1(128.55,118.51) v1@128.55,118.578 ; v1(128.55,121.75) v1@128.55,121.682 ; C10.1@128.823,114.475 v1(129.725,114.475) ; C2.1@129.4,127.775 v1(129.4,128.45) ; U34.37@129.5,30 U34.11@130.75,30 ; C49.1@130.225,76.375 130.225,75.575 130.65,75.15 U28.N1@130.725,75.15 v4(130.325,74.75) ; U28.N9@130.725,68.75 130.735,68.74 130.735,68.59 v4(131.125,68.2) ; v4@131.125,68.297 v4(131.125,68.2) ; U28.M9@131.525,68.75 131.525,68.6 v4(131.125,68.2) ; v1(131.7,22.9) U41.1@131.7,24.15 v1(131.7,25.4) ; C50.1@132.825,76.325 132.825,76.3 133.294,75.832 133.294,75.741 133.332,75.703 133.332,75.649 133.151,75.468 U28.K1@133.151,75.153 ; C84.1@132.95,67.45 132.95,67.893 133,67.943 133,68.05 v4(133.1,68.15) 133.125,68.175 U28.K9@133.125,68.75 ; C150.1@134.15,21.05 v1(134.15,22.195) ; C48.1@134.675,76.375 134.675,75.75 v4(134.725,75.7) U28.H1@134.725,75.15 ; v4(134.7,68.2) 134.7,68.725 U28.H9@134.725,68.75 ; U28.F1@136.325,75.15 v4(136.725,75.55) U28.E1@137.132,75.143 ; R63.1@137.075,67.55 137.075,68.025 136.9,68.2 136.9,68.525 U28.E9@137.125,68.75 v4(136.75,69.125) 137.125,69.5 U28.E8@137.125,69.55 U28.D8@137.925,69.55 U28.C9@138.725,68.75 v4(138.725,68.2) 138.725,67.6 C82.1@138.775,67.55 138.793,67.533 138.793,66.558 C85.1@138.925,66.425 ; C1.1@137.2,127.796 v1(137.2,128.471) ; U44.2@137.5,19.525 v1(137.5,20.195) ; U28.A8@140.325,69.55 140.325,69.526 140.631,69.526 140.729,69.623 140.874,69.623 v4(140.875,69.625) ; U28.A2@140.325,74.35 v4(140.725,74.75) ; v1(144.3,132.6) CN1.12@145.25,132.6 ; v1(145.25,131.1) CN1.12@145.25,132.6 ; v1(145.25,134.1) CN1.12@145.25,132.625 ; v1(152.1,118.84) U8.3@152.1,119.52 ; U8.8@152.1,120.34 v1(152.1,121.02) ; v1(153.175,116.245) C8.1@153.175,116.925 ; C6.1@154.95,120.48 v1(155.6,120.48) ; R62.1@155.455,68.5 v1(155.455,69.175) ; TP34.1@155.546,19.25 155.546,18.296 155.943,17.9 v1(156.675,17.9) ; v1(156.25,121.27) CN1.6@156.25,122.5 v1(156.25,123.73) ; v1(157.375,118.84) U9.3@157.375,119.52 ; U9.8@157.375,120.34 v1(157.375,121.02) ; v1(160.75,121.87) CN1.10@160.75,123.1 v1(161.725,123.1) ; v1(160.775,131.1) CN1.11@160.775,132.575 ; v1(160.775,134.1) CN1.11@160.775,132.6 ; U50.12@161.15,9.125 161.15,10.575 v1(161.637,11.063) ; C62.1@161.7,66.675 v1(161.7,67.35) ; v1(161.725,132.6) CN1.11@160.775,132.6 ; v1(161.947,19.525) CN15.A1@162.7,19.525 ; v1(161.947,25.025) CN15.A12@162.7,25.025 ; v1(162.687,10.012) 162.725,10.05 U50.16@163.575,10.05 ; CN15.B12@164.4,19.275 164.505,19.17 164.505,18.25 CN15.SH1@164.61,18.145 ; CN15.B1@164.4,24.775 164.412,24.775 164.412,25.312 v1(164.425,25.325) ; R327.1@165.525,15.4 165.537,15.413 166.312,15.413 v1(166.325,15.425) ; C69.2@170.125,65.1 v1(170.125,65.775) ; v1(12.625,26.5) U37.9@14.525,26.5 v1(16.425,26.5) ; U37.8@13.325,28.4 13.325,28.652 13.048,28.652 12.648,29.052 12.423,29.052 v1(12.375,29.1) v1(12.375,28.4) U37.8@13.325,28.4 ; v1@128.55,118.578 128.3,118.828 CN3.27@128.3,120.13 128.3,121.432 v1@128.55,121.682 ; v1@128.55,118.578 128.8,118.828 CN3.29@128.8,120.13 128.8,121.432 v1@128.55,121.682 ; CN1.12@145.25,132.6 CN1.12@145.25,132.625 ; CN1.12@145.25,132.6 145.275,132.6 CN1.12@145.25,132.625 ; CN1.11@160.775,132.575 CN1.11@160.775,132.6 ; CN1.11@160.775,132.575 CN1.11@160.75,132.6 CN1.11@160.775,132.6
  Top Layer w0.4: U37.4@15.725,24.6 15.725,24.25 15.925,24.05 R204.1@15.925,23.25 v1(16.7,23.25) ; v1(63.45,43.59) 63.455,43.585 CN22.9@65.465,43.585 ; v1(63.45,46.13) 63.455,46.125 CN22.5@65.465,46.125 ; v1(63.45,47.4) 63.455,47.395 CN22.3@65.465,47.395
  Top Layer w0.5: SB2.1@16.722,82.425 v1(17.522,82.425) ; SB3.1@16.725,46.65 v1(17.525,46.65) ; v1(29.025,34.225) C110.1@29.875,34.225 ; v1(29.395,28.4) C129.1@30.17,28.4 ; C169.1@29.52,8.225 v1(29.52,9) ; v1(30.52,31.275) U35.2@31.57,31.275 v1(32.62,31.275) ; v1(30.875,12.375) U49.2@31.925,12.375 v1(32.975,12.375) ; v1(31.725,4.2) U52.9@31.725,5.4 v1(31.725,6.6) ; v1(137.587,36.7) CN13.43@139,36.7 v1(140.412,36.7) ; v1(137.587,39.1) CN13.37@139,39.1 v1(140.412,39.1) ; v1(137.587,39.9) CN13.35@139,39.9 v1(140.412,39.9) ; v1(137.587,42.3) CN13.29@139,42.3 v1(140.412,42.3) ; v1(137.587,43.1) CN13.27@139,43.1 v1(140.412,43.1) ; v1(137.587,51.1) CN13.15@139,51.1 v1(140.412,51.1) ; v1(137.587,53.5) CN13.9@139,53.5 v1(140.412,53.5) ; v1(137.6,45.5) CN13.21@139,45.5 v1(140.425,45.5) ; v1(145.787,33.9) CN13.50@147.2,33.9 v1(148.612,33.9) ; v1(145.787,37.9) CN13.40@147.2,37.9 v1(148.612,37.9) ; v1(145.787,40.3) CN13.34@147.2,40.3 v1(148.612,40.3) ; v1(145.787,43.5) CN13.26@147.2,43.5 v1(148.612,43.5) ; v1(145.787,46.7) CN13.18@147.2,46.7 v1(148.612,46.7) ; v1(145.787,55.5) CN13.4@147.2,55.5 v1(148.612,55.5) ; v1(151.18,66.875) U30.2@151.855,66.875 U30.EP@153.155,66.875 ; v1(152.309,69.925) C76.1@153.05,69.925 ; v1(152.314,64.225) C89.1@153.055,64.225 ; v1(153.155,65.125) U30.EP@153.155,66.875 ; v1(153.155,68.625) U30.EP@153.155,66.875
  Top Layer w0.55: v1(5.475,31.6) C118.1@6.4,31.6 ; v1(5.5,33.65) C114.1@6.425,33.65 ; v1(6.4,30.225) C118.1@6.4,31.6 ; v1(6.425,35.025) C114.1@6.425,33.65 ; C114.1@6.45,33.675 C114.1@6.425,33.65 ; v1(13.725,19.325) C148.1@13.725,20.9 ; C116.1@15.15,32.1 v1(15.15,33) ; C116.1@15.975,32.1 v1(15.975,33) ; C117.1@16.95,32.1 v1(16.95,33) ; v1(17.35,26.95) C130.1@17.35,27.65 ; C117.1@17.775,32.1 v1(17.775,33) ; C164.2@38.25,13.6 v1(38.25,14.375) ; U48.2@39.5,13.925 v1(39.5,14.725) ; v1(156.675,17.9) C159.1@157.575,17.9 ; v1(157.275,20.5) U43.2@158.075,20.5 ; v1(157.625,19.25) C156.1@158.4,19.25 ; C118.1@6.4,31.6 C118.1@6.425,31.625 C114.1@6.425,33.65
  Top Layer w0.8: v1(23.225,78.7) 24.475,78.7 C42.2@24.5,78.675 ; C147.2@151.025,21.575 v1(152.275,21.575)
  Bottom Layer w0.1: C231.1@92.35,70.327 C231.1@92.35,70.45
  Bottom Layer w0.15: C212.1@89.65,73.775 89.65,73.381 89.6,73.331 89.6,72.799 v2(90,72.4)
  Bottom Layer w0.2: C329.2@34.225,21.05 34.425,21.25 v2(34.8,21.25) ; v2(34.8,21.9) 35.175,21.9 C328.2@35.375,21.7 ; C297.2@34.8,26.85 35.2,26.45 v2(35.45,26.45) ; v2(36.75,22.55) 37.175,22.55 C324.2@37.325,22.7 ; C289.2@36.75,27.5 37.15,27.5 v2(37.4,27.75) ; C282.2@38.05,29.925 v1(38.05,30.6) ; C303.2@38.125,25.15 v2(38.7,25.15) ; C299.2@38.25,26.45 38.25,26.425 38.405,26.27 38.583,26.27 38.7,26.153 v2(38.7,25.8) ; C327.2@39.3,22.15 39.3,22.65 ; C281.2@39.35,29.925 v1(39.35,30.6) ; v1(40.65,19.05) C333.2@40.65,19.725 ; v2(40.65,24.5) 40.875,24.275 C311.2@41.2,24.275 ; v1(40.65,26.825) C290.2@40.65,27.5 ; C326.2@41.455,22.8 41.455,23.3 ; 41.578,23.505 42.07,23.505 42.17,23.405 42.195,23.405 42.35,23.25 C325.2@42.35,23.225 ; v2(42.6,25.15) 42.85,24.9 C310.2@42.85,24.5 ; v2(42.6,26.45) 42.6,27.158 42.717,27.275 C298.2@43.25,27.275 ; C314.1@59.445,24.02 59.87,24.02 v1(60.2,24.35) ; C306.1@59.7,24.95 60.325,24.95 ; C323.1@60.8,23.825 60.8,24.45 ; 60.8,26.625 C296.1@60.8,27.25 ; v1(61.365,20.75) C332.1@62.125,20.75 ; C322.1@62,23.825 62,24.45 ; R305.1@63.075,34.75 v1(63.075,35.425) ; 63.2,26.625 C295.1@63.2,27.25 ; C317.1@63.25,23.95 63.25,24.575 ; C309.1@64.075,24.9 64.075,25.525 ; R293.1@66.125,40.85 v1(66.125,41.525) ; R292.1@67.15,40.85 v1(67.15,41.525) ; v1(67.275,35.425) 67.275,34.867 67.392,34.75 R303.1@68.075,34.75 ; C313.1@84.445,24.02 84.87,24.02 v1(85.2,24.35) ; C305.1@84.7,24.95 85.325,24.95 ; C321.1@85.8,23.825 85.8,24.45 ; 85.8,26.625 C294.1@85.8,27.25 ; v1(86.365,20.75) C331.1@87.125,20.75 ; C320.1@87,23.825 87,24.45 ; C244.1@87.375,69.425 87.375,69.075 87.65,68.8 87.9,68.8 88.3,68.4 v2(88.4,68.4) ; v2(87.6,80.42) 88.03,80.85 88.825,80.85 ; C192.1@87.8,78.1 87.862,78.038 88.362,78.038 v2(88.4,78) 88.405,77.996 88.405,77.854 88.205,77.655 88.18,77.655 88.163,77.655 88.075,77.567 C194.1@88.075,77.2 ; R302.1@88.075,34.75 v1(88.075,35.425) ; 88.2,26.625 C293.1@88.2,27.25 ; C316.1@88.25,23.95 88.25,24.575 ; R251.2@88.825,80.3 88.825,80.85 ; C235.1@88.9,70.125 89.075,70.3 C234.1@89.575,70.3 89.625,70.3 89.962,70.636 89.962,70.761 v2(90,70.8) ; C308.1@89.075,24.9 89.075,25.525 ; C225.1@89.7,71.8 89.8,71.9 89.8,72.147 90,72.346 v2(90,72.4) ; C201.1@89.717,75.842 89.717,76.117 ; C201.1@89.75,75.825 89.75,76.084 89.717,76.117 ; R250.2@89.875,80.3 89.875,80.75 89.775,80.85 88.825,80.85 ; R296.1@90.15,34.75 R295.1@91.125,34.75 R294.1@92.075,34.75 ; C196.1@90.575,76.925 90.525,76.925 v2(90,76.4) 89.725,76.125 89.717,76.117 ; C190.1@91.425,79.375 91.425,78.955 91.6,78.781 v2(91.6,78.775) ; C271.1@91.675,36.15 91.675,36.125 91.83,35.97 91.855,35.97 92.031,35.794 ; v1(92.075,35.425) R294.1@92.075,34.75 ; v1@92.086,35.436 92.086,35.761 92.295,35.97 92.32,35.97 92.475,36.125 C270.1@92.475,36.15 ; R300.1@93.075,34.75 R294.1@92.075,34.75 ; v2(93.201,75.6) C195.1@93.201,76.4 ; C246.1@96.75,67.8 96.75,67.75 96.45,67.45 R274.2@96.45,66.825 96.45,66.225 96.775,65.9 97.3,65.9 97.35,65.95 97.444,65.95 97.456,65.962 97.721,65.962 97.862,65.962 v2(97.9,66) ; v1(106.7,85.175) C181.1@106.7,85.9 ; v1(107.825,85.175) C182.1@107.825,85.9 ; C312.1@109.445,24.02 109.87,24.02 v1(110.2,24.35) ; C304.1@109.7,24.95 110.325,24.95 ; C319.1@110.8,23.825 110.8,24.45 ; 110.8,26.625 C292.1@110.8,27.25 ; v1(111.365,20.75) C330.1@112.125,20.75 ; C318.1@112,23.825 112,24.45 ; R299.1@113.075,34.75 v1(113.075,35.425) ; 113.2,26.625 C291.1@113.2,27.25 ; C315.1@113.25,23.95 113.25,24.575 ; C307.1@114.1,24.9 114.1,25.525 ; R307.1@115.075,31.6 R306.1@116.075,31.6 ; v1(117.075,35.425) 117.075,34.867 117.192,34.75 R297.1@118.075,34.75
  Bottom Layer w0.25: C174.1@55.725,128.725 55.725,129.425 v1(55.75,129.45)
  Bottom Layer w0.3: R322.1@59.05,27.2 59.875,27.2 ; C280.2@59.325,30.3 v1(60.15,30.3) ; C302.1@59.35,26.025 60.175,26.025 ; 62.075,26.625 C288.1@62.075,27.45 ; R305.1@63.075,34.75 R304.1@64.075,34.75 ; v1(71.725,72.125) R96.2@72.375,72.125 ; R321.1@84.05,27.2 84.875,27.2 ; C279.2@84.325,30.3 v1(85.15,30.3) ; C301.1@84.35,26.025 85.175,26.025 ; v2(86.194,79.6) 86.2,79.6 C191.1@86.625,79.175 ; C250.1@87.025,66.15 87.025,66.575 87.2,66.75 v2(87.65,66.75) ; 87.075,26.625 C287.1@87.075,27.45 ; R302.1@88.075,34.75 R301.1@89.075,34.75 ; v2(88.37,66.944) 88.375,66.938 C248.1@88.375,66.4 ; C197.1@89.2,76.125 89.725,76.125 v2(90,76.4) ; C205.1@90.5,74.5 90.725,74.5 91.025,74.8 C207.1@91.2,74.8 v2(91.6,74.8) ; C241.2@90.925,69.6 90.925,69.85 v2(90.8,69.975) 90.925,70.1 C233.2@90.925,70.388 90.925,70.675 v2(90.8,70.8) 90.925,70.925 C228.1@90.925,71.2 ; C271.1@91.553,36.28 91.57,36.28 91.675,36.175 C271.1@91.675,36.15 ; v2(91.6,72.4) 91.725,72.275 C221.1@92.025,72.275 ; C193.1@91.6,78.25 v2@91.6,78.775 ; C214.1@92.1,73.65 92.1,73.7 v2(92.4,74) ; C231.1@92.35,70.327 92.381,70.296 92.381,70.021 92.4,70.002 v2(92.4,69.975) ; C231.1@92.35,70.45 92.375,70.475 92.375,70.748 92.4,70.773 v2(92.4,70.8) ; v2@92.4,69.948 92.425,69.923 92.425,69.605 C240.1@92.475,69.555 ; v2@92.525,69.216 C240.1@92.525,69.6 ; C204.2@92.825,75.25 92.825,75.4 93.025,75.6 v2(93.201,75.6) ; C210.1@93.101,74.475 93.101,74.725 93.351,74.975 93.351,75.45 v2(93.201,75.6) ; v2(93.2,73.175) 93.175,73.175 93.1,73.1 C219.2@93.1,72.825 93.1,72.55 93.225,72.425 93.304,72.425 93.45,72.279 93.45,72.2 93.575,72.075 C223.1@93.575,72 ; 93.65,71.775 93.825,71.6 v2(94,71.6) ; C199.1@93.775,75.875 93.476,75.875 v2(93.201,75.6) ; C213.1@93.876,73.65 93.876,73.875 v2(94.001,74) ; C222.1@94.125,72 94,71.875 v2(94,71.6) ; C220.1@94.675,72.775 95.201,72.775 v2(95.601,72.375) 95.625,72.375 C224.1@96.026,71.974 ; C220.1@94.676,72.825 94.676,73.075 94.751,73.15 v2(94.801,73.15) ; C208.1@94.7,74.48 94.7,74.718 v2(94.832,74.85) ; C242.1@94.75,69.575 94.8,69.625 v2(94.8,70) ; C215.2@95.507,73.625 95.507,73.9 v2(95.607,74) ; v2@95.607,73.999 C216.1@96.081,73.524 ; v2@95.607,75.6 95.607,75.575 95.907,75.875 C200.2@96.075,75.875 ; v2(95.625,70) v2(94.8,70) ; v2@95.625,70.025 95.75,70.15 C230.2@96.675,70.15 96.7,70.125 96.961,70.125 97.05,70.036 v2(97.05,70) 96.65,69.6 96.55,69.6 96.5,69.55 96.5,69.327 96.4,69.227 v2(96.4,69.2) ; C209.1@96.438,74.513 96.475,74.55 v2(96.475,74.85) 96.9,74.85 96.95,74.9 96.95,74.523 R262.1@97.324,74.149 ; C218.1@96.649,72.831 96.649,72.849 96.624,72.874 96.632,72.875 96.925,72.582 96.925,72.575 v2(97.125,72.375) 97.145,72.394 97.245,72.394 C217.1@97.5,72.65 ; C227.1@96.65,71.275 96.875,71.275 v2(97.175,71.575) ; v2@97.2,70 97.25,69.95 C237.1@97.45,69.95 ; 98.65,61.1 98.65,61.125 98.755,61.23 98.78,61.23 98.95,61.4 R287.2@98.95,62.075 99,62.125 v2(100.5,62.125) ; v2(98.7,62.825) 98.7,62.835 98.85,62.985 C253.1@98.85,65 ; C260.1@100.05,64.675 C252.1@100.05,65.675 100.05,66.2 C249.1@99.925,66.325 100.256,66.656 v2@100.381,66.656 ; R285.1@101.2,63.8 102.05,63.8 v4(102.4,63.45) ; C189.1@102.72,79.846 102.72,81.145 v4@102.75,81.175 ; v1(103.566,104.941) 103.666,104.841 C175.1@103.666,104.216 ; v4(107,60.175) 107,59.675 C264.1@107.15,59.525 ; C180.1@108.4,88.475 108.4,89.049 108.643,89.292 108.727,89.292 v1(108.775,89.34) ; R320.1@109.05,27.2 109.875,27.2 ; C278.1@109.325,30.3 v1(110.15,30.3) ; C300.1@109.35,26.025 110.175,26.025 ; C177.1@110.35,92.025 110.425,91.95 v1(110.425,91.275) ; 112.075,26.625 C286.1@112.075,27.45 ; R299.1@113.075,34.75 R298.1@114.075,34.75 ; C178.1@113.275,90.45 113.279,90.446 113.829,90.446 113.9,90.375 114.275,90.375 v1(114.3,90.35) ; v1(114.35,88.85) 115.15,88.85 C179.1@115.225,88.925 ; v1(115.975,30.925) 116.006,30.956 116.006,31.531 R306.1@116.075,31.6 ; v4(116.9,68.575) 116.9,69.6 C236.1@117.098,69.798 ; v4(121.1,61.075) 121.1,61.15 C262.1@121.7,61.75 ; C247.1@121.675,66.975 v4@122.3,67.6 ; v4(122.3,67.625) v4@122.3,67.6 ; C245.1@122.975,68.25 122.95,68.25 v4@122.3,67.6 ; C284.1@125.925,29.5 125.925,29.525 126.03,29.63 126.299,29.63 126.552,29.883 126.552,30.052 v1(126.6,30.1) ; C275.1@125.925,33 126.5,33 v1(126.6,32.9) ; v4(127.05,63.525) 127.05,63.05 C261.1@127.2,62.9 ; R324.1@127.89,24.675 v1(127.89,25.5) ; C285.1@128,29.425 v1(128,30.1) ; v1(128,32.9) C273.1@128,33.575 ; v4(128.65,63.075) C259.1@128.65,63.7 ; R323.1@129.16,24.675 v1(129.16,25.5) ; v1(129.4,30.1) 130,29.5 C283.1@130.075,29.5 ; C277.1@130.075,31.125 130.075,31.15 129.97,31.255 129.701,31.255 129.456,31.5 v1(129.4,31.5) 129.448,31.548 129.448,31.617 129.701,31.87 129.97,31.87 130.075,31.975 C276.1@130.075,32 ; v4(130.55,63.075) C258.1@130.55,63.7 ; R252.1@132.025,79.3 132.025,79.975 132.575,80.525 133.075,80.525 v4(133.1,80.55) 133.113,80.538 133.113,79.838 C188.1@133.125,79.825 ; v4(132.45,63.075) C257.1@132.45,63.7 ; v4(134.35,63.075) C256.1@134.35,63.7 ; C187.1@135.675,79.925 v4(135.675,80.55) ; v4(136.25,63.075) C255.1@136.25,63.7 ; C186.1@137.575,79.925 v4(137.575,80.55) ; v1(137.587,36.7) 137.687,36.8 C269.1@138.25,36.8 ; v4(138.45,62.925) C254.1@138.45,63.65 ; C185.1@139.475,79.925 v4(139.475,80.55) ; C268.2@139.75,39 140.313,39 v1(140.412,39.1) ; C239.1@140.25,69.55 140.85,69.55 140.875,69.575 141.475,69.575 C238.1@141.525,69.625 ; C226.1@140.55,71.25 140.648,71.347 141.025,71.347 141.3,71.623 v4(141.3,71.675) ; v4(140.725,74.75) 140.764,74.788 140.839,74.788 141.345,75.295 141.37,75.295 141.475,75.4 C202.1@141.475,75.425 ; C184.1@140.925,79.925 140.95,79.95 v4(140.95,80.575) ; C202.1@141.45,75.425 141.45,76.1 C198.1@141.513,76.163 ; C183.1@142.575,79.95 v4(142.575,80.6) ; C211.1@142.625,73.675 v4(143.25,73.675) ; C274.2@147.9,33.55 148.262,33.55 v1(148.612,33.9) 148.262,34.25 C272.2@147.9,34.25 ; C266.2@147.9,55.15 148.262,55.15 v1(148.612,55.5) 148.262,55.85 C265.2@147.9,55.85 ; C267.2@147.95,43.4 148.513,43.4 v1(148.612,43.5) ; 161.45,12.113 C335.2@161.45,12.85 ; v1(162.712,12.113) 162.85,12.25 C334.2@162.85,12.85 ; v2(94,71.6) v2(94.8,70.8) 94.725,70.725 C232.1@94.725,70.425 94.725,70.075 v2(94.8,70)
  Bottom Layer w0.4: v1(33.28,45.265) 33.285,45.26 CN25.9@35.295,45.26 ; v1@59.045,45.26 CN25.8@61.055,45.26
